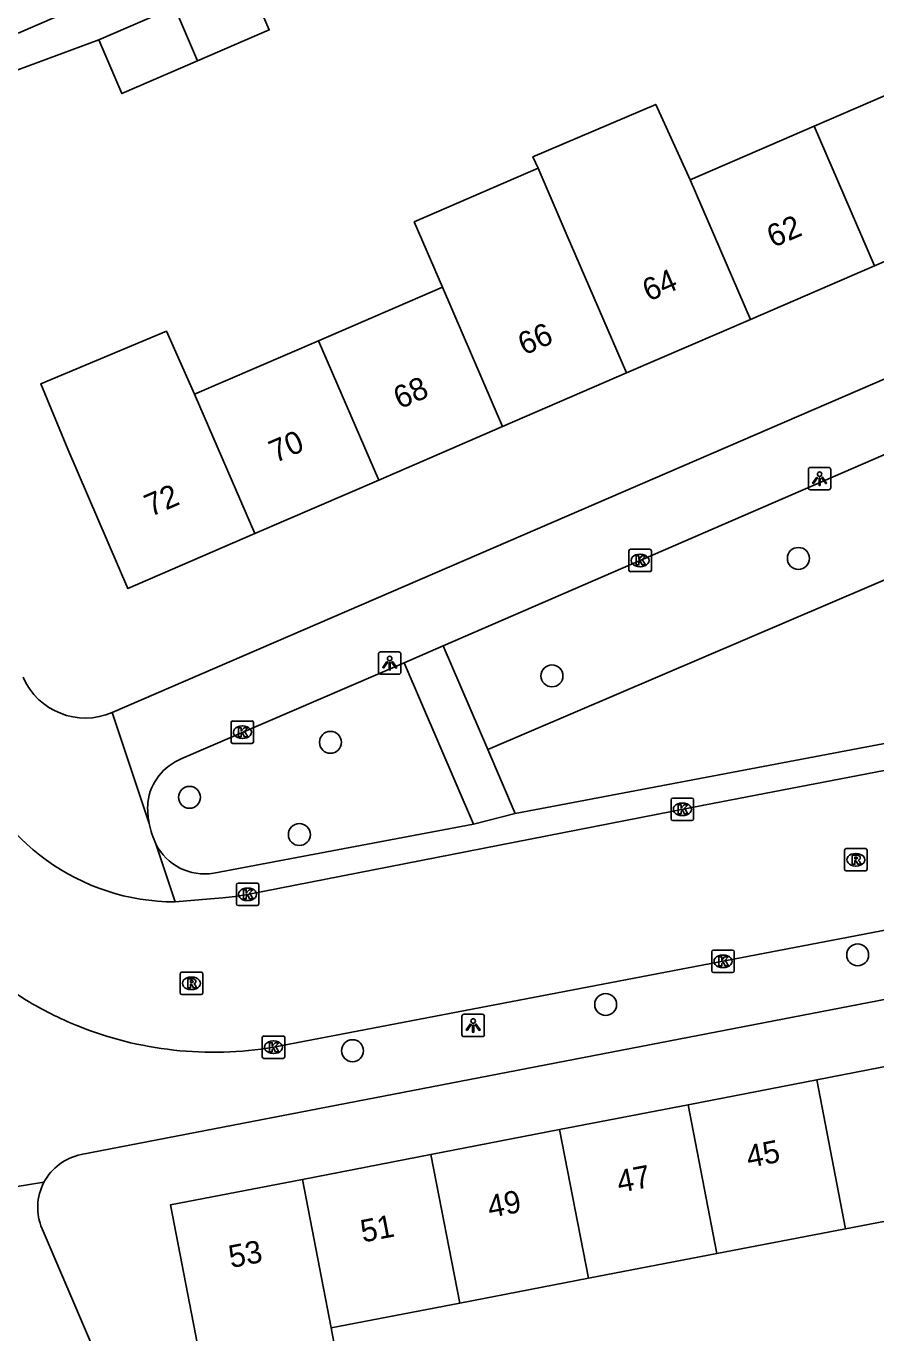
# Model space of a CAD drawing. Extents: x 159353 to 160616, y 385893 to 387321.
# Drawn here: x 159688.4 to 159726.2, y 386300.6 to 386358.8 of the extents above; entities that cross this region are included whole.
import ezdxf

# ---------------------------------------------------------------- set-up
doc = ezdxf.new("R2010")
doc.units = 0
for name, color, linetype in [('IMGEO_Boom', 7, 'Continuous'), ('IMGEO_Groenvoorziening', 7, 'Continuous'), ('IMGEO_Kolk', 7, 'Continuous'), ('IMGEO_Lichtpunt', 7, 'Continuous'), ('IMGEO_Pand', 7, 'Continuous'), ('IMGEO_Pand_nummerreeks', 7, 'Continuous'), ('IMGEO_Rijbaan_lokaal_open', 7, 'Continuous'), ('IMGEO_Rioolput', 7, 'Continuous'), ('IMGEO_Voetpad_open', 7, 'Continuous')]:
    doc.layers.add(name, color=color, linetype=linetype)

msp = doc.modelspace()

# ---------------------------------------------------------------- linework, layer by layer
at = {"layer": 'IMGEO_Boom'}
for centre in [(159722.781, 386335.11), (159711.799, 386329.875), (159701.929, 386326.915), (159695.648, 386324.464), (159700.545, 386322.805), (159725.42, 386317.443), (159714.192, 386315.231), (159702.914, 386313.171)]:
    msp.add_circle(centre, 0.489, dxfattribs=at)
at = {"layer": 'IMGEO_Groenvoorziening'}
msp.add_lwpolyline([(159729.923, 386335.56), (159708.936, 386326.592)], dxfattribs=at)
at = {"layer": 'IMGEO_Kolk'}
for p, q in [((159715.227, 386334.594), (159715.227, 386335.446)), ((159715.302, 386335.52), (159716.154, 386335.52)), ((159715.715, 386335.3), (159715.74, 386335.3)), ((159716.228, 386335.446), (159716.228, 386334.594)), ((159715.738, 386334.74), (159715.713, 386334.74)), ((159716.154, 386334.52), (159715.302, 386334.52)), ((159697.504, 386326.939), (159697.504, 386327.791)), ((159697.579, 386327.865), (159698.431, 386327.865)), ((159697.992, 386327.645), (159698.017, 386327.645)), ((159698.505, 386327.791), (159698.505, 386326.939)), ((159698.015, 386327.085), (159697.99, 386327.085)), ((159698.431, 386326.865), (159697.579, 386326.865)), ((159717.109, 386323.504), (159717.109, 386324.356)), ((159717.184, 386324.43), (159718.036, 386324.43)), ((159717.597, 386324.21), (159717.622, 386324.21)), ((159718.11, 386324.356), (159718.11, 386323.504)), ((159717.62, 386323.65), (159717.595, 386323.65)), ((159718.036, 386323.43), (159717.184, 386323.43)), ((159697.811, 386320.642), (159698.663, 386320.642)), ((159697.736, 386319.716), (159697.736, 386320.568)), ((159698.224, 386320.422), (159698.249, 386320.422)), ((159698.737, 386320.568), (159698.737, 386319.716)), ((159698.663, 386319.642), (159697.811, 386319.642)), ((159698.247, 386319.862), (159698.222, 386319.862)), ((159718.92, 386316.731), (159718.92, 386317.583)), ((159718.995, 386317.657), (159719.847, 386317.657)), ((159719.408, 386317.437), (159719.433, 386317.437)), ((159719.921, 386317.583), (159719.921, 386316.731)), ((159719.847, 386316.657), (159718.995, 386316.657)), ((159719.431, 386316.877), (159719.406, 386316.877)), ((159698.89, 386312.902), (159698.89, 386313.754)), ((159698.965, 386313.828), (159699.817, 386313.828)), ((159699.378, 386313.608), (159699.403, 386313.608)), ((159699.891, 386313.754), (159699.891, 386312.902)), ((159699.401, 386313.048), (159699.376, 386313.048)), ((159699.817, 386312.828), (159698.965, 386312.828))]:
    msp.add_line(p, q, dxfattribs=at)
for points in [[(159715.227, 386334.594), (159715.227, 386335.446)], [(159715.302, 386335.52), (159716.154, 386335.52)], [(159715.548, 386335.22), (159715.671, 386335.22), (159715.671, 386335.069), (159715.801, 386335.22), (159715.965, 386335.22), (159715.819, 386335.069), (159715.972, 386334.82), (159715.82, 386334.82), (159715.735, 386334.984), (159715.671, 386334.917), (159715.671, 386334.82), (159715.548, 386334.82), (159715.548, 386335.22)], [(159716.228, 386335.446), (159716.228, 386334.594)], [(159716.154, 386334.52), (159715.302, 386334.52)], [(159697.504, 386326.939), (159697.504, 386327.791)], [(159697.579, 386327.865), (159698.431, 386327.865)], [(159697.825, 386327.565), (159697.948, 386327.565), (159697.948, 386327.414), (159698.078, 386327.565), (159698.242, 386327.565), (159698.096, 386327.414), (159698.249, 386327.165), (159698.097, 386327.165), (159698.012, 386327.329), (159697.948, 386327.262), (159697.948, 386327.165), (159697.825, 386327.165), (159697.825, 386327.565)], [(159698.505, 386327.791), (159698.505, 386326.939)], [(159698.431, 386326.865), (159697.579, 386326.865)], [(159717.109, 386323.504), (159717.109, 386324.356)], [(159717.184, 386324.43), (159718.036, 386324.43)], [(159717.43, 386324.13), (159717.553, 386324.13), (159717.553, 386323.979), (159717.683, 386324.13), (159717.847, 386324.13), (159717.701, 386323.979), (159717.854, 386323.73), (159717.702, 386323.73), (159717.617, 386323.894), (159717.553, 386323.827), (159717.553, 386323.73), (159717.43, 386323.73), (159717.43, 386324.13)], [(159718.11, 386324.356), (159718.11, 386323.504)], [(159718.036, 386323.43), (159717.184, 386323.43)], [(159697.811, 386320.642), (159698.663, 386320.642)], [(159697.736, 386319.716), (159697.736, 386320.568)], [(159698.057, 386320.342), (159698.18, 386320.342), (159698.18, 386320.191), (159698.31, 386320.342), (159698.474, 386320.342), (159698.328, 386320.191), (159698.481, 386319.942), (159698.329, 386319.942), (159698.244, 386320.106), (159698.18, 386320.039), (159698.18, 386319.942), (159698.057, 386319.942), (159698.057, 386320.342)], [(159698.737, 386320.568), (159698.737, 386319.716)], [(159698.663, 386319.642), (159697.811, 386319.642)], [(159718.92, 386316.731), (159718.92, 386317.583)], [(159718.995, 386317.657), (159719.847, 386317.657)], [(159719.241, 386317.357), (159719.364, 386317.357), (159719.364, 386317.206), (159719.494, 386317.357), (159719.658, 386317.357), (159719.512, 386317.206), (159719.665, 386316.957), (159719.513, 386316.957), (159719.428, 386317.121), (159719.364, 386317.054), (159719.364, 386316.957), (159719.241, 386316.957), (159719.241, 386317.357)], [(159719.921, 386317.583), (159719.921, 386316.731)], [(159719.847, 386316.657), (159718.995, 386316.657)], [(159698.89, 386312.902), (159698.89, 386313.754)], [(159698.965, 386313.828), (159699.817, 386313.828)], [(159699.891, 386313.754), (159699.891, 386312.902)], [(159699.211, 386313.528), (159699.334, 386313.528), (159699.334, 386313.377), (159699.464, 386313.528), (159699.628, 386313.528), (159699.482, 386313.377), (159699.635, 386313.128), (159699.483, 386313.128), (159699.398, 386313.292), (159699.334, 386313.225), (159699.334, 386313.128), (159699.211, 386313.128), (159699.211, 386313.528)], [(159699.817, 386312.828), (159698.965, 386312.828)]]:
    msp.add_lwpolyline(points, dxfattribs=at)
for centre, start, end in [((159715.304, 386335.444), 91.55205, 178.44795), ((159715.304, 386335.444), 91.55205, 178.44795), ((159716.152, 386335.444), 1.55205, 88.44795), ((159716.152, 386335.444), 1.55205, 88.44795), ((159715.304, 386334.596), 181.55205, 268.44795), ((159715.304, 386334.596), 181.55205, 268.44795), ((159716.152, 386334.596), 271.55205, 358.44795), ((159716.152, 386334.596), 271.55205, 358.44795), ((159697.581, 386327.789), 91.55205, 178.44795), ((159697.581, 386327.789), 91.55205, 178.44795), ((159698.429, 386327.789), 1.55205, 88.44795), ((159698.429, 386327.789), 1.55205, 88.44795), ((159697.581, 386326.941), 181.55205, 268.44795), ((159697.581, 386326.941), 181.55205, 268.44795), ((159698.429, 386326.941), 271.55205, 358.44795), ((159698.429, 386326.941), 271.55205, 358.44795), ((159717.186, 386324.354), 91.55205, 178.44795), ((159717.186, 386324.354), 91.55205, 178.44795), ((159718.034, 386324.354), 1.55205, 88.44795), ((159718.034, 386324.354), 1.55205, 88.44795), ((159717.186, 386323.506), 181.55205, 268.44795), ((159717.186, 386323.506), 181.55205, 268.44795), ((159718.034, 386323.506), 271.55205, 358.44795), ((159718.034, 386323.506), 271.55205, 358.44795), ((159697.813, 386320.566), 91.55205, 178.44795), ((159697.813, 386320.566), 91.55205, 178.44795), ((159698.661, 386320.566), 1.55205, 88.44795), ((159698.661, 386320.566), 1.55205, 88.44795), ((159697.813, 386319.718), 181.55205, 268.44795), ((159697.813, 386319.718), 181.55205, 268.44795), ((159698.661, 386319.718), 271.55205, 358.44795), ((159698.661, 386319.718), 271.55205, 358.44795), ((159718.997, 386317.581), 91.55205, 178.44795), ((159718.997, 386317.581), 91.55205, 178.44795), ((159719.845, 386317.581), 1.55205, 88.44795), ((159719.845, 386317.581), 1.55205, 88.44795), ((159718.997, 386316.733), 181.55205, 268.44795), ((159718.997, 386316.733), 181.55205, 268.44795), ((159719.845, 386316.733), 271.55205, 358.44795), ((159719.845, 386316.733), 271.55205, 358.44795), ((159698.967, 386313.752), 91.55205, 178.44795), ((159698.967, 386313.752), 91.55205, 178.44795), ((159699.815, 386313.752), 1.55205, 88.44795), ((159699.815, 386313.752), 1.55205, 88.44795), ((159698.967, 386312.904), 181.55205, 268.44795), ((159698.967, 386312.904), 181.55205, 268.44795), ((159699.815, 386312.904), 271.55205, 358.44795), ((159699.815, 386312.904), 271.55205, 358.44795)]:
    msp.add_arc(centre, 0.0765, start, end, dxfattribs=at)
for centre, major_axis, ratio, start_param, end_param in [((159715.714, 386335.02), (-0.387, 0.002), 0.722429, 4.712389, 7.853982), ((159715.739, 386335.02), (-0.39, 0.002), 0.717154, 1.570796, 4.712389), ((159697.991, 386327.365), (-0.387, 0.002), 0.722429, 4.712389, 7.853982), ((159698.016, 386327.365), (-0.39, 0.002), 0.717154, 1.570796, 4.712389), ((159717.596, 386323.93), (-0.387, 0.002), 0.722429, 4.712389, 7.853982), ((159717.621, 386323.93), (-0.39, 0.002), 0.717154, 1.570796, 4.712389), ((159698.223, 386320.142), (-0.387, 0.002), 0.722429, 4.712389, 7.853982), ((159698.248, 386320.142), (-0.39, 0.002), 0.717154, 1.570796, 4.712389), ((159719.407, 386317.157), (-0.387, 0.002), 0.722429, 4.712389, 7.853982), ((159719.432, 386317.157), (-0.39, 0.002), 0.717154, 1.570796, 4.712389), ((159699.377, 386313.328), (-0.387, 0.002), 0.722429, 4.712389, 7.853982), ((159699.402, 386313.328), (-0.39, 0.002), 0.717154, 1.570796, 4.712389)]:
    msp.add_ellipse(centre, major_axis=major_axis, ratio=ratio, start_param=start_param, end_param=end_param, dxfattribs=at)
at = {"layer": 'IMGEO_Lichtpunt'}
for p, q in [((159723.225, 386339.069), (159723.225, 386338.262)), ((159723.225, 386339.069), (159723.225, 386338.262)), ((159724.127, 386339.164), (159723.319, 386339.164)), ((159724.127, 386339.164), (159723.319, 386339.164)), ((159724.221, 386338.262), (159724.221, 386339.069)), ((159724.221, 386338.262), (159724.221, 386339.069)), ((159723.319, 386338.168), (159724.127, 386338.168)), ((159723.319, 386338.168), (159724.127, 386338.168)), ((159704.07, 386330.851), (159704.07, 386330.044)), ((159704.07, 386330.851), (159704.07, 386330.044)), ((159704.972, 386330.946), (159704.164, 386330.946)), ((159704.972, 386330.946), (159704.164, 386330.946)), ((159705.066, 386330.044), (159705.066, 386330.851)), ((159705.066, 386330.044), (159705.066, 386330.851)), ((159704.164, 386329.95), (159704.972, 386329.95)), ((159704.164, 386329.95), (159704.972, 386329.95)), ((159708.692, 386314.796), (159707.884, 386314.796)), ((159708.692, 386314.796), (159707.884, 386314.796)), ((159707.79, 386314.701), (159707.79, 386313.894)), ((159707.79, 386314.701), (159707.79, 386313.894)), ((159708.786, 386313.894), (159708.786, 386314.701)), ((159708.786, 386313.894), (159708.786, 386314.701)), ((159707.884, 386313.8), (159708.692, 386313.8)), ((159707.884, 386313.8), (159708.692, 386313.8))]:
    msp.add_line(p, q, dxfattribs=at)
for points in [[(159723.599, 386338.733), (159723.638, 386338.705), (159723.45, 386338.443), (159723.412, 386338.47), (159723.599, 386338.733)], [(159723.701, 386338.685), (159723.748, 386338.685), (159723.748, 386338.363), (159723.701, 386338.363), (159723.701, 386338.685)], [(159723.811, 386338.705), (159723.849, 386338.732), (159724.036, 386338.47), (159723.997, 386338.442), (159723.811, 386338.705)], [(159704.444, 386330.515), (159704.483, 386330.487), (159704.295, 386330.225), (159704.257, 386330.252), (159704.444, 386330.515)], [(159704.656, 386330.487), (159704.694, 386330.514), (159704.881, 386330.252), (159704.842, 386330.224), (159704.656, 386330.487)], [(159704.546, 386330.467), (159704.593, 386330.467), (159704.593, 386330.145), (159704.546, 386330.145), (159704.546, 386330.467)], [(159708.164, 386314.365), (159708.203, 386314.337), (159708.015, 386314.075), (159707.977, 386314.102), (159708.164, 386314.365)], [(159708.266, 386314.317), (159708.313, 386314.317), (159708.313, 386313.995), (159708.266, 386313.995), (159708.266, 386314.317)], [(159708.376, 386314.337), (159708.414, 386314.364), (159708.601, 386314.102), (159708.562, 386314.074), (159708.376, 386314.337)]]:
    msp.add_lwpolyline(points, dxfattribs=at)
for centre in [(159723.724, 386338.867), (159704.569, 386330.649), (159708.289, 386314.499)]:
    msp.add_circle(centre, 0.0994, dxfattribs=at)
for centre, start, end in [((159723.319, 386339.069), 90, 180), ((159723.319, 386339.069), 90, 180), ((159724.127, 386339.069), 0, 90), ((159724.127, 386339.069), 0, 90), ((159723.319, 386338.262), 180, 270), ((159723.319, 386338.262), 180, 270), ((159724.127, 386338.262), 270, 0), ((159724.127, 386338.262), 270, 360), ((159704.164, 386330.851), 90, 180), ((159704.164, 386330.851), 90, 180), ((159704.972, 386330.851), 0, 90), ((159704.972, 386330.851), 0, 90), ((159704.164, 386330.044), 180, 270), ((159704.164, 386330.044), 180, 270), ((159704.972, 386330.044), 270, 0), ((159704.972, 386330.044), 270, 360), ((159707.884, 386314.701), 90, 180), ((159707.884, 386314.701), 90, 180), ((159708.692, 386314.701), 0, 90), ((159708.692, 386314.701), 0, 90), ((159707.884, 386313.894), 180, 270), ((159707.884, 386313.894), 180, 270), ((159708.692, 386313.894), 270, 0), ((159708.692, 386313.894), 270, 360)]:
    msp.add_arc(centre, 0.0946, start, end, dxfattribs=at)
at = {"layer": 'IMGEO_Pand'}
for points in [[(159698.168, 386361.048), (159699.199, 386358.662), (159696.011, 386357.285)], [(159691.604, 386358.213), (159694.981, 386359.671)], [(159696.011, 386357.285), (159694.981, 386359.671)], [(159696.011, 386357.285), (159692.635, 386355.827), (159691.604, 386358.213)], [(159723.479, 386354.37), (159729.046, 386356.779), (159731.735, 386350.555), (159726.166, 386348.148)], [(159711.181, 386352.498), (159710.949, 386353.006), (159716.422, 386355.339), (159717.959, 386351.98)], [(159717.959, 386351.98), (159723.479, 386354.37)], [(159723.479, 386354.37), (159726.166, 386348.148)], [(159706.918, 386347.202), (159705.66, 386350.109), (159711.181, 386352.498)], [(159711.181, 386352.498), (159712.439, 386349.591), (159715.124, 386343.375)], [(159720.645, 386345.761), (159717.959, 386351.98)], [(159726.166, 386348.148), (159720.645, 386345.761)], [(159701.398, 386344.813), (159706.918, 386347.202)], [(159706.918, 386347.202), (159709.602, 386340.988)], [(159720.645, 386345.761), (159715.124, 386343.375)], [(159698.56, 386336.215), (159692.902, 386333.769), (159690.221, 386339.975), (159689.018, 386342.895), (159694.629, 386345.236), (159695.878, 386342.423)], [(159695.878, 386342.423), (159701.398, 386344.813)], [(159701.398, 386344.813), (159704.081, 386338.601)], [(159715.124, 386343.375), (159709.602, 386340.988)], [(159698.56, 386336.215), (159695.878, 386342.423)], [(159709.602, 386340.988), (159704.081, 386338.601)], [(159704.081, 386338.601), (159698.56, 386336.215)], [(159729.325, 386312.984), (159723.596, 386311.876)], [(159717.866, 386310.767), (159723.596, 386311.876)], [(159723.596, 386311.876), (159724.883, 386305.233)], [(159712.137, 386309.658), (159717.866, 386310.767)], [(159717.866, 386310.767), (159719.151, 386304.131)], [(159706.407, 386308.55), (159712.137, 386309.658)], [(159713.421, 386303.03), (159712.137, 386309.658)], [(159700.678, 386307.441), (159706.407, 386308.55)], [(159707.689, 386301.928), (159706.407, 386308.55)], [(159700.678, 386307.441), (159694.802, 386306.304), (159696.082, 386299.697), (159697, 386296.28), (159702.621, 386297.319), (159701.958, 386300.826)], [(159701.958, 386300.826), (159700.678, 386307.441)], [(159724.883, 386305.233), (159730.613, 386306.334)], [(159724.883, 386305.233), (159719.151, 386304.131)], [(159719.151, 386304.131), (159713.421, 386303.03)], [(159713.421, 386303.03), (159707.689, 386301.928)], [(159707.689, 386301.928), (159701.958, 386300.826)]]:
    msp.add_lwpolyline(points, dxfattribs=at)
at = {"layer": 'IMGEO_Rijbaan_lokaal_open'}
for points in [[(159695.01, 386319.802), (159696.59, 386319.944), (159697.141, 386319.982), (159697.689, 386320.047), (159698.233, 386320.14), (159718.56, 386324.115), (159738.888, 386328.014), (159739.679, 386328.083), (159741.27, 386328.208)], [(159741.903, 386321.475), (159725.01, 386318.226), (159699.395, 386313.33)], [(159688.37, 386315.426), (159687.739, 386315.836)]]:
    msp.add_lwpolyline(points, dxfattribs=at)
for centre, radius, start, end in [((159695.027, 386329.622), 9.82, 198.4392, 269.90124), ((159696.601, 386329.042), 15.91, 238.8468, 247.96229), ((159696.708, 386329.221), 16.116, 247.84793, 279.59799)]:
    msp.add_arc(centre, radius, start, end, dxfattribs=at)
at = {"layer": 'IMGEO_Rioolput'}
for p, q in [((159724.841, 386321.256), (159724.841, 386322.108)), ((159724.916, 386322.182), (159725.768, 386322.182)), ((159725.329, 386321.962), (159725.354, 386321.962)), ((159725.842, 386322.108), (159725.842, 386321.256)), ((159725.768, 386321.182), (159724.916, 386321.182)), ((159725.352, 386321.402), (159725.327, 386321.402)), ((159695.235, 386315.75), (159695.235, 386316.602)), ((159695.31, 386316.676), (159696.162, 386316.676)), ((159696.236, 386316.602), (159696.236, 386315.75)), ((159695.723, 386316.456), (159695.748, 386316.456)), ((159696.162, 386315.676), (159695.31, 386315.676)), ((159695.746, 386315.896), (159695.721, 386315.896))]:
    msp.add_line(p, q, dxfattribs=at)
for points in [[(159724.841, 386321.256), (159724.841, 386322.108)], [(159724.916, 386322.182), (159725.768, 386322.182)], [(159725.43, 386321.88), (159725.178, 386321.882), (159725.178, 386321.482)], [(159725.356, 386321.801), (159725.302, 386321.801), (159725.302, 386321.72)], [(159725.842, 386322.108), (159725.842, 386321.256)], [(159725.768, 386321.182), (159724.916, 386321.182)], [(159725.178, 386321.482), (159725.302, 386321.482), (159725.302, 386321.644), (159725.313, 386321.644)], [(159725.302, 386321.72), (159725.354, 386321.72)], [(159725.36, 386321.615), (159725.431, 386321.482), (159725.571, 386321.482), (159725.506, 386321.608)], [(159695.235, 386315.75), (159695.235, 386316.602)], [(159695.31, 386316.676), (159696.162, 386316.676)], [(159696.236, 386316.602), (159696.236, 386315.75)], [(159695.824, 386316.374), (159695.572, 386316.376), (159695.572, 386315.976)], [(159695.572, 386315.976), (159695.696, 386315.976), (159695.696, 386316.138), (159695.707, 386316.138)], [(159695.75, 386316.295), (159695.696, 386316.295), (159695.696, 386316.214)], [(159695.696, 386316.214), (159695.748, 386316.214)], [(159695.754, 386316.109), (159695.825, 386315.976), (159695.965, 386315.976), (159695.9, 386316.102)], [(159696.162, 386315.676), (159695.31, 386315.676)]]:
    msp.add_lwpolyline(points, dxfattribs=at)
for centre, radius, start, end in [((159724.918, 386322.106), 0.0765, 91.55205, 178.44795), ((159724.918, 386322.106), 0.0765, 91.55205, 178.44795), ((159725.362, 386321.705), 0.0964, 77.00612, 93.18647), ((159725.376, 386321.762), 0.0378, 276.66336, 79.67722), ((159725.429, 386321.77), 0.109, 350.36119, 89.41601), ((159725.427, 386321.77), 0.112, 277.58423, 350.98172), ((159725.766, 386322.106), 0.0765, 1.55205, 88.44795), ((159725.766, 386322.106), 0.0765, 1.55205, 88.44795), ((159724.918, 386321.258), 0.0765, 181.55205, 268.44795), ((159724.918, 386321.258), 0.0765, 181.55205, 268.44795), ((159725.312, 386321.591), 0.0533, 26.02933, 88.69889), ((159725.338, 386321.909), 0.19, 274.7715, 282.96867), ((159725.411, 386321.555), 0.108, 29.51342, 73.79051), ((159725.766, 386321.258), 0.0765, 271.55205, 358.44795), ((159725.766, 386321.258), 0.0765, 271.55205, 358.44795), ((159695.312, 386316.6), 0.0765, 91.55205, 178.44795), ((159695.312, 386316.6), 0.0765, 91.55205, 178.44795), ((159696.16, 386316.6), 0.0765, 1.55205, 88.44795), ((159696.16, 386316.6), 0.0765, 1.55205, 88.44795), ((159695.706, 386316.085), 0.0533, 26.02933, 88.69889), ((159695.732, 386316.403), 0.19, 274.7715, 282.96867), ((159695.756, 386316.199), 0.0964, 77.00612, 93.18647), ((159695.77, 386316.256), 0.0378, 276.66336, 79.67722), ((159695.823, 386316.264), 0.109, 350.36119, 89.41601), ((159695.821, 386316.264), 0.112, 277.58423, 350.98172), ((159695.805, 386316.049), 0.108, 29.51342, 73.79051), ((159695.312, 386315.752), 0.0765, 181.55205, 268.44795), ((159695.312, 386315.752), 0.0765, 181.55205, 268.44795), ((159696.16, 386315.752), 0.0765, 271.55205, 358.44795), ((159696.16, 386315.752), 0.0765, 271.55205, 358.44795)]:
    msp.add_arc(centre, radius, start, end, dxfattribs=at)
for centre, major_axis, ratio, start_param, end_param in [((159725.328, 386321.682), (-0.387, 0.002), 0.722429, 4.712389, 7.853982), ((159725.353, 386321.682), (-0.39, 0.002), 0.717154, 1.570796, 4.712389), ((159695.722, 386316.176), (-0.387, 0.002), 0.722429, 4.712389, 7.853982), ((159695.747, 386316.176), (-0.39, 0.002), 0.717154, 1.570796, 4.712389)]:
    msp.add_ellipse(centre, major_axis=major_axis, ratio=ratio, start_param=start_param, end_param=end_param, dxfattribs=at)
at = {"layer": 'IMGEO_Voetpad_open'}
for points in [[(159700.758, 386366.874), (159701.797, 386364.467), (159688.018, 386358.522)], [(159687.18, 386356.583), (159691.604, 386358.213)], [(159735.891, 386347.111), (159692.209, 386328.247)], [(159706.953, 386331.217), (159727.896, 386340.285)], [(159706.953, 386331.217), (159705.213, 386330.452)], [(159708.936, 386326.592), (159706.953, 386331.217)], [(159695.307, 386326.187), (159705.213, 386330.452)], [(159705.213, 386330.452), (159708.306, 386323.269)], [(159693.852, 386323.293), (159692.209, 386328.247)], [(159733.123, 386328.099), (159710.157, 386323.745)], [(159710.157, 386323.745), (159708.936, 386326.592)], [(159708.306, 386323.269), (159710.157, 386323.745)], [(159708.306, 386323.269), (159696.73, 386321.082)], [(159695.01, 386319.802), (159694.149, 386322.393)], [(159690.827, 386308.544), (159742.393, 386318.498)], [(159684.675, 386306.593), (159689.161, 386307.308)], [(159700.131, 386281.311), (159697.471, 386285.615), (159689.082, 386305.236)]]:
    msp.add_lwpolyline(points, dxfattribs=at)
for centre, radius, start, end in [((159691.006, 386331.022), 3.025, 203.53962, 293.44013), ((159696.192, 386323.936), 2.419, 111.46507, 172.81753), ((159697.531, 386324.001), 3.747, 176.37323, 190.89267), ((159697.554, 386324.016), 3.772, 191.04567, 205.48011), ((159696.325, 386323.481), 2.433, 206.56351, 279.58057), ((159691.283, 386306.189), 2.399, 100.95576, 152.18744), ((159691.283, 386306.19), 2.398, 152.20312, 203.42991)]:
    msp.add_arc(centre, radius, start, end, dxfattribs=at)

# ---------------------------------------------------------------- texts
at = {"layer": 'IMGEO_Pand_nummerreeks'}
for s, rotation, p in [('62', 23.37696, (159721.652, 386348.942)), ('64', 23.37668, (159716.107, 386346.545)), ('66', 23.37668, (159710.56, 386344.147)), ('68', 23.37696, (159705.015, 386341.75)), ('70', 23.37696, (159699.468, 386339.352)), ('72', 23.37668, (159693.914, 386336.952)), ('45', 10.95171, (159720.564, 386307.948)), ('47', 10.95171, (159714.797, 386306.832)), ('49', 10.95171, (159709.031, 386305.717)), ('51', 10.95171, (159703.375, 386304.622)), ('53', 10.94922, (159697.497, 386303.485))]:
    msp.add_text(s, height=1, rotation=rotation, dxfattribs=at).set_placement(p)

doc.saveas('drawing.dxf')
